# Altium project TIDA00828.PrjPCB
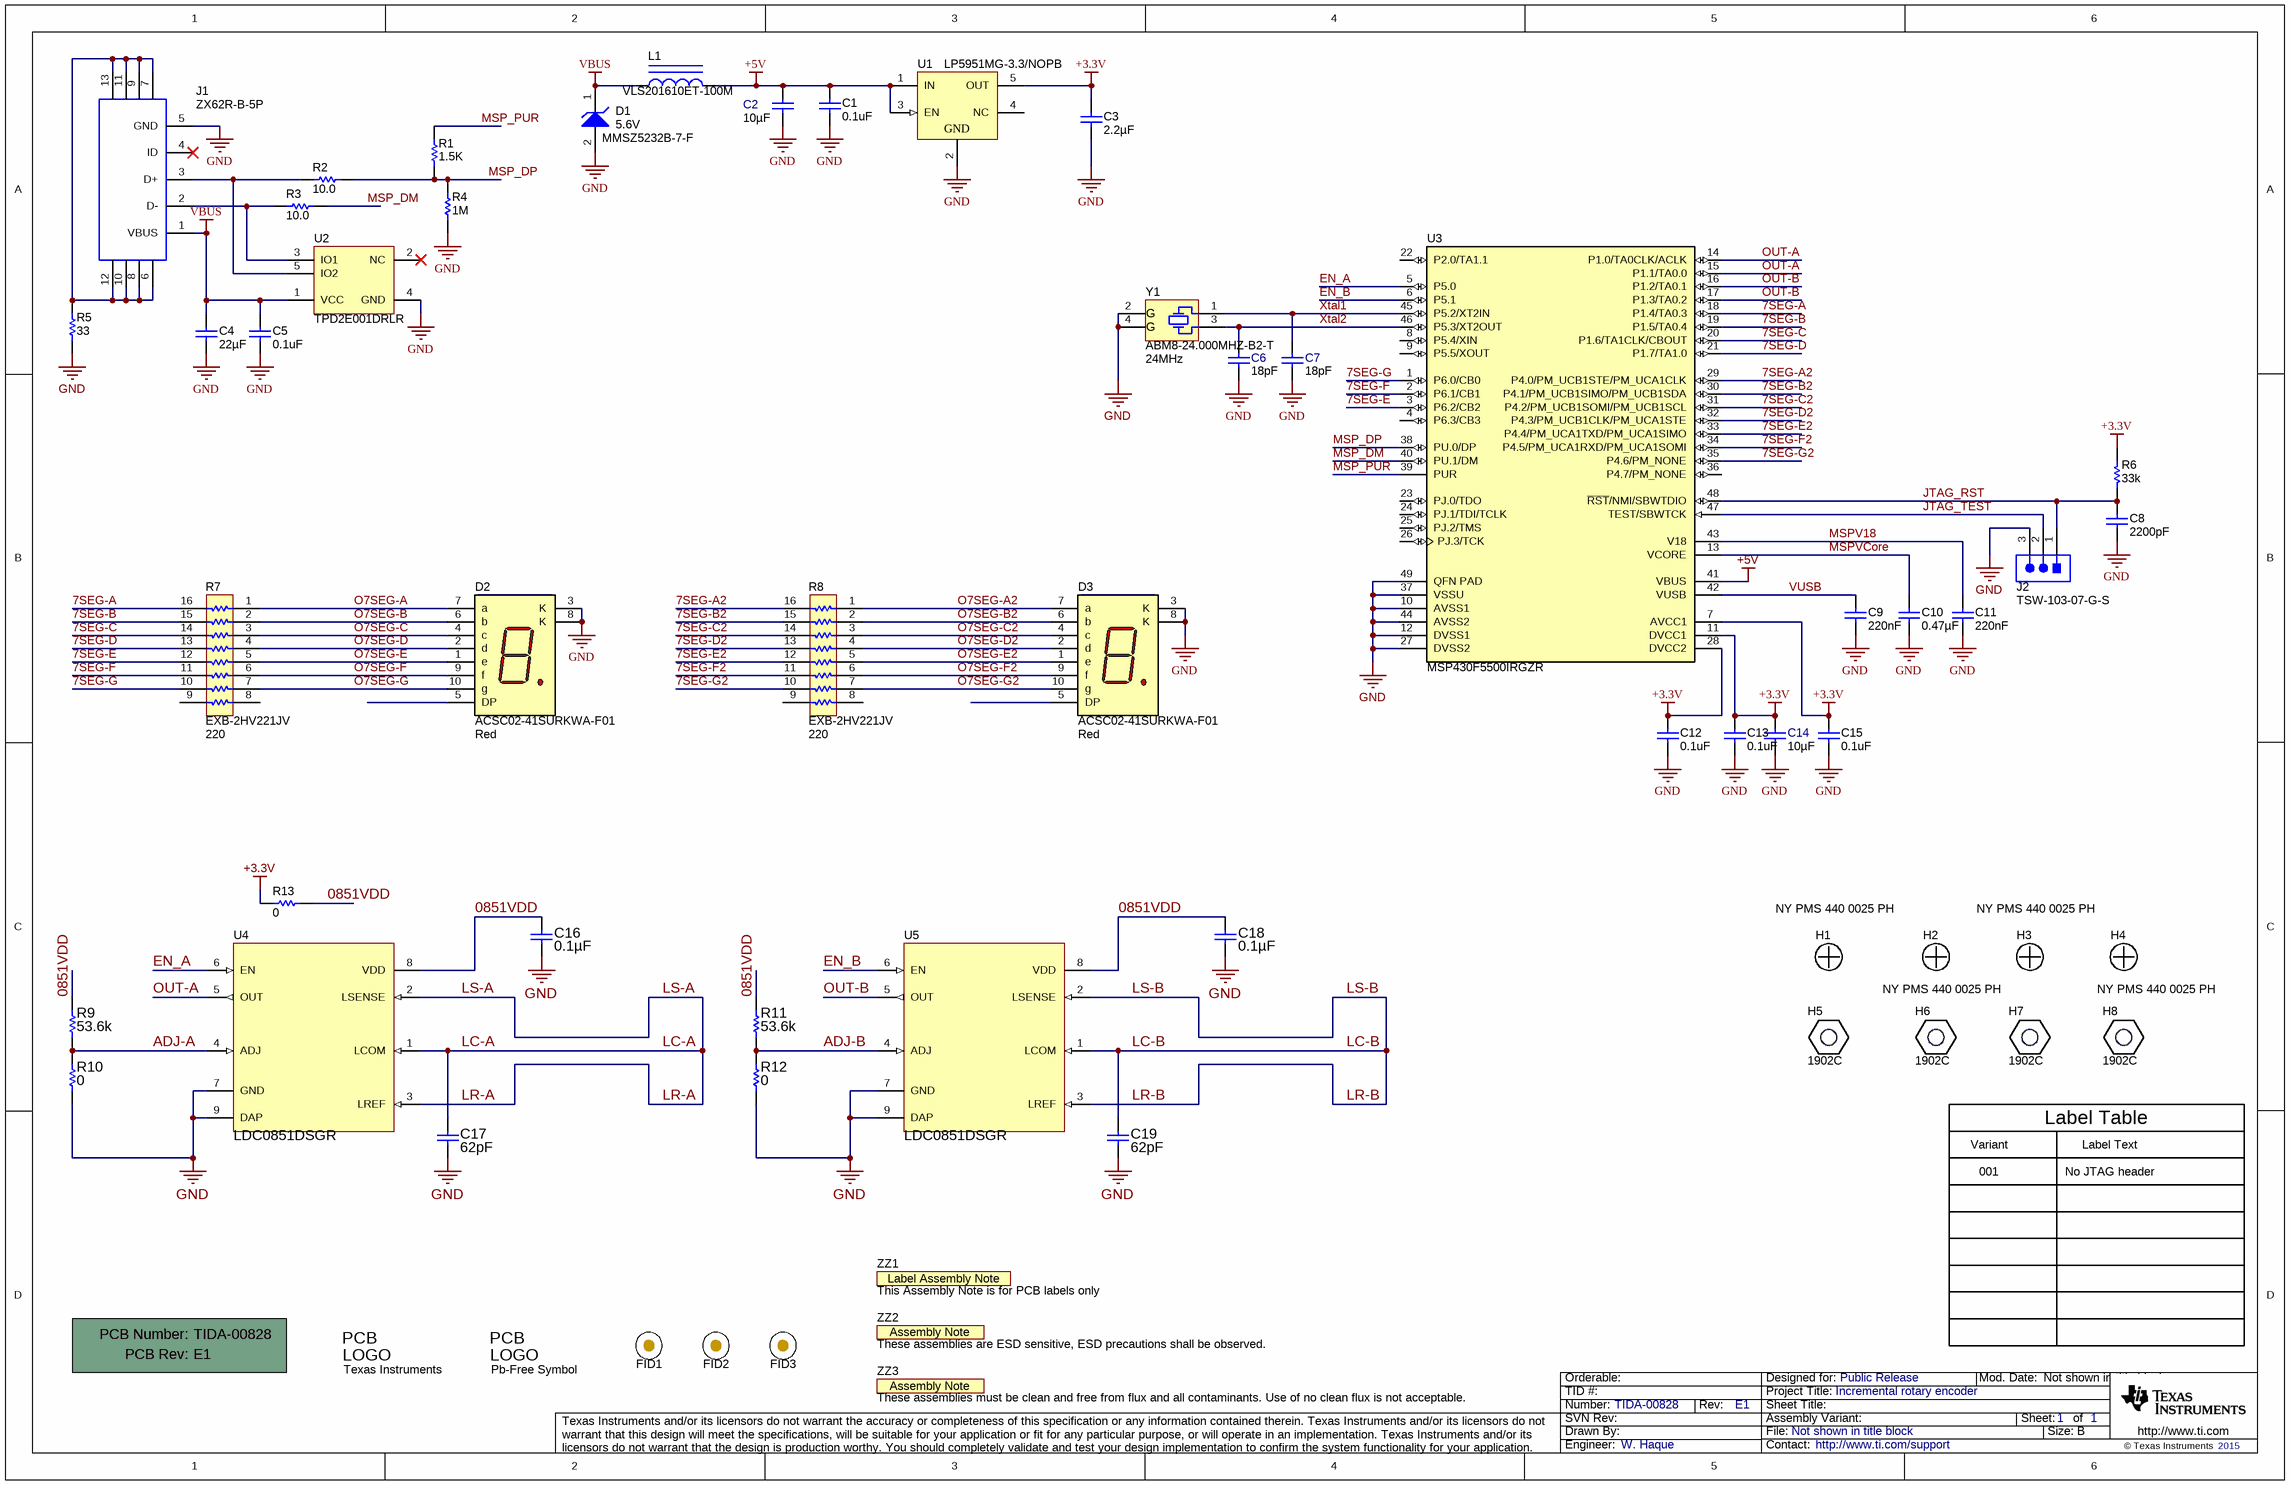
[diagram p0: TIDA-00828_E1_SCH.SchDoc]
TechSupport: http://www.ti.com/support; SCH_Rev: E1; PRJ_Title: Incremental rotary encoder; PRJ_Number: TIDA-00828; PRJ_Engineer: W. Haque; PRJ_Customer: Public Release; PCB_Rev: E1; PCB_Layout: W. Haque; CopyrightYear: 2015
1 sheet, 61 parts. Net scope: global (net labels, ports and power ports of the same name join across sheets).
Board file: TIDA-00828_E1.PcbDoc

## Sheet TIDA-00828_E1_SCH.SchDoc
size 431 x 279 mm; Date: Not shown in title block; ApprovedBy: Not shown in title block; CheckedBy: Not shown in title block; Author: Not shown in title block; CompanyName: Not shown in title block; Engineer: Not shown in title block; Organization: Not shown in title block; Address1: Not shown in title block; Address2: Not shown in title block; Address3: Not shown in title block; Address4: Not shown in title block; DocumentNumber: 1; Revision: Use project parameter SCH_Rev; SheetNumber: 1; SheetTotal: 1; PageSetup: Record=PageOptions¦CenterHorizontal=True¦CenterVertical=True¦PrintScale=1.00¦XCorrection=1.00¦YCorrection=1.00¦PrintKind=0¦BorderSize=5000000¦LeftOffset=0¦BottomOffset=0¦Orientation=2¦PaperLength=1000¦PaperWidth=1000¦Scale=100¦PaperSource=15¦PrintQuality=600¦MediaType=1¦DitherType=10¦PaperKind=Letter¦PrintScaleMode=1

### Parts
!PCB1  Printed Circuit Board  (value not drawn)  (mechanical)
C1  value 0.1uF  [0402]  (hidden comment: GRM155R71C104JA88D)
C2  ValueDisplayed: 10µF  [0603]  (hidden comment: C1608X5R1A106M)
C3  ValueDisplayed: 2.2µF  [0603]  (hidden comment: C0603C225K8PACTU)
C4  ValueDisplayed: 22µF  [0805_HV]  (hidden comment: C2012X5R1C226K125AC)
C5  value 0.1uF  [0402]  (hidden comment: GRM155R71C104JA88D)
C6  ValueDisplayed: 18pF  [0603]  (hidden comment: GRM1885C2A180JA01D)
C7  ValueDisplayed: 18pF  [0603]  (hidden comment: GRM1885C2A180JA01D)
C8  ValueDisplayed: 2200pF  [0603]  (hidden comment: C0603X222K5RACTU)
C9  value 220nF  [0402]  (hidden comment: C1005X7R1A224K050BB)
C10  ValueDisplayed: 0.47µF  [0402]  (hidden comment: GRM155R60J474KE19D)
C11  value 220nF  [0402]  (hidden comment: C1005X7R1A224K050BB)
C12  value 0.1uF  [0402]  (hidden comment: GRM155R71C104JA88D)
C13  value 0.1uF  [0402]  (hidden comment: GRM155R71C104JA88D)
C14  ValueDisplayed: 10µF  [0603]  (hidden comment: C1608X5R1A106M)
C15  value 0.1uF  [0402]  (hidden comment: GRM155R71C104JA88D)
C16  ValueDisplayed: 0.1µF  [0402]  (hidden comment: GRM155R71C104KA88D)
C17  ValueDisplayed: 62pF  [0402]  (hidden comment: GRM1555C1H620JA01D)
C18  ValueDisplayed: 0.1µF  [0402]  (hidden comment: GRM155R71C104KA88D)
C19  ValueDisplayed: 62pF  [0402]  (hidden comment: GRM1555C1H620JA01D)
D1  MMSZ5232B-7-F  value 5.6V  [SOD-123]
D2  ACSC02-41SURKWA-F01  value Red  [ACSC02-41_Red]
D3  ACSC02-41SURKWA-F01  value Red  [ACSC02-41_Red]
FID1  Fiducial  [Fiducial10-20]  (value not drawn)
FID2  Fiducial  [Fiducial10-20]  (value not drawn)
FID3  Fiducial  [Fiducial10-20]  (value not drawn)
H1  NY PMS 440 0025 PH  [NY PMS 440 0025 PH]
H2  NY PMS 440 0025 PH  [NY PMS 440 0025 PH]
H3  NY PMS 440 0025 PH  [NY PMS 440 0025 PH]
H4  NY PMS 440 0025 PH  [NY PMS 440 0025 PH]
H5  1902C  [Keystone_1902C]
H6  1902C  [Keystone_1902C]
H7  1902C  [Keystone_1902C]
H8  1902C  [Keystone_1902C]
J1  ZX62R-B-5P  [Hirose_ZX62R-B-5P]
J2  TSW-103-07-G-S  [TSW-103-07-G-S]
L1  VLS201610ET-100M  [VLS201610ET]
Logo1  Texas Instruments  [TI_Stacked_Overlay_Small]  (no BOM)
Logo2  Pb-Free Symbol  [Pb-Free_Overlay_Small]  (no BOM)
R1  value 1.5K  [0402]  (hidden comment: CRCW04021K50JNED)
R2  ValueDisplayed: 10.0  [0402]  (hidden comment: CRCW040210R0FKED)
R3  ValueDisplayed: 10.0  [0402]  (hidden comment: CRCW040210R0FKED)
R4  value 1M  [0402]  (hidden comment: RC0402JR-071ML)
R5  value 33  [0603]  (hidden comment: CRCW060333R0JNEA)
R6  value 33k  [0402]  (hidden comment: CRCW040233K0JNED)
R7  EXB-2HV221JV  ValueDisplayed: 220  [RESCAXS_EXB-2HV]
R8  EXB-2HV221JV  ValueDisplayed: 220  [RESCAXS_EXB-2HV]
R9  ValueDisplayed: 53.6k  [0402]  (hidden comment: CRCW040253K6FKED)
R10  ValueDisplayed: 0  [0402]  (hidden comment: RC0402JR-070RL)
R11  ValueDisplayed: 53.6k  [0402]  (hidden comment: CRCW040253K6FKED)
R12  ValueDisplayed: 0  [0402]  (hidden comment: RC0402JR-070RL)
R13  ValueDisplayed: 0  [0402]  (hidden comment: RC0402JR-070RL)
U1  LP5951MG-3.3/NOPB  [MAA05A_N]
U2  TPD2E001DRLR  [DRL0005A]
U3  MSP430F5500IRGZR  [RGZ0048A]
U4  LDC0851DSGR  [DSG0008A]
U5  LDC0851DSGR  [DSG0008A]
Y1  ABM8-24.000MHZ-B2-T  Frequency: 24MHz  [XTAL_ABM8]
ZZ1  This Assembly Note is for PCB labels only  [AssemblyNoteLabel]  (no BOM)
ZZ2  These assemblies are ESD sensitive, ESD precautions shall be observed.  [AssemblyNote]  (no BOM)
ZZ3  These assemblies must be clean and free from flux and all contaminants. Use of no clean flux is not acceptable.  [AssemblyNote]  (no BOM)

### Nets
+3.3V: C3.1 C12.1 C13.1 C14.1 C15.1 R6.1 R13.1 U1.5(OUT) U3.7(AVCC1) U3.11(DVCC1) U3.28(DVCC2)
+5V: C1.1 C2.1 L1.2 U1.1(IN) U1.3(EN) U3.41(VBUS)
GND: C1.2 C2.2 C3.2 C4.2 C5.2 C6.1 C7.1 C8.1 C9.2 C10.2 C11.2 C12.2 C13.2 C14.2 C15.2 C16.2 C17.2 C18.2 C19.2 D1.2(A) D2.3(K) D2.8(K) D3.3(K) D3.8(K) J1.5(GND) J2.3 R4.1 R5.1 R10.1 R12.1 U1.2(GND) U2.4(GND) U3.10(AVSS1) U3.12(DVSS1) U3.27(DVSS2) U3.37(VSSU) U3.44(AVSS2) U3.49(QFN_PAD) U4.7(GND) U4.9(DAP) U5.7(GND) U5.9(DAP) Y1.2(GND) Y1.4(GND)
VBUS: C4.1 C5.1 D1.1(K) J1.1(VBUS) L1.1 U2.1(VCC)
7SEG-A: R7.16 U3.18(P1.4/TA0.3)
7SEG-A2: R8.16 U3.29(P4.0/PM_UCB1STE/PM_UCA1CLK)
7SEG-B: R7.15 U3.19(P1.5/TA0.4)
7SEG-B2: R8.15 U3.30(P4.1/PM_UCB1SIMO/PM_UCB1SDA)
7SEG-C: R7.14 U3.20(P1.6/TA1CLK/CBOUT)
7SEG-C2: R8.14 U3.31(P4.2/PM_UCB1SOMI/PM_UCB1SCL)
7SEG-D: R7.13 U3.21(P1.7/TA1.0)
7SEG-D2: R8.13 U3.32(P4.3/PM_UCB1CLK/PM_UCA1STE)
7SEG-E: R7.12 U3.3(P6.2/CB2)
7SEG-E2: R8.12 U3.33(P4.4/PM_UCA1TXD/PM_UCA1SIMO)
7SEG-F: R7.11 U3.2(P6.1/CB1)
7SEG-F2: R8.11 U3.34(P4.5/PM_UCA1RXD/PM_UCA1SOMI)
7SEG-G: R7.10 U3.1(P6.0/CB0)
7SEG-G2: R8.10 U3.35(P4.6/PM_NONE)
0851VDD: C16.1 C18.1 R9.2 R11.2 R13.2 U4.8(VDD) U5.8(VDD)
ADJ-A: R9.1 R10.2 U4.4(ADJ)
ADJ-B: R11.1 R12.2 U5.4(ADJ)
EN_A: U3.5(P5.0) U4.6(EN)
EN_B: U3.6(P5.1) U5.6(EN)
JTAG_RST: C8.2 J2.1 R6.2 U3.48(~{RST}/NMI/SBWTDIO)
JTAG_TEST: J2.2 U3.47(TEST/SBWTCK)
LC-A: C17.1 U4.1(LCOM) U4.2(LSENSE) U4.3(LREF)  [also labelled LR-A, LS-A]
LC-B: C19.1 U5.1(LCOM) U5.2(LSENSE) U5.3(LREF)  [also labelled LR-B, LS-B]
MSP_DM: R3.2 U3.40(PU.1/DM)
MSP_DP: R1.1 R2.2 R4.2 U3.38(PU.0/DP)
MSP_PUR: R1.2 U3.39(PUR)
MSPV18: C11.1 U3.43(V18)
MSPVCore: C10.1 U3.13(VCORE)
O7SEG-A: D2.7(a) R7.1
O7SEG-A2: D3.7(a) R8.1
O7SEG-B: D2.6(b) R7.2
O7SEG-B2: D3.6(b) R8.2
O7SEG-C: D2.4(c) R7.3
O7SEG-C2: D3.4(c) R8.3
O7SEG-D: D2.2(d) R7.4
O7SEG-D2: D3.2(d) R8.4
O7SEG-E: D2.1(e) R7.5
O7SEG-E2: D3.1(e) R8.5
O7SEG-F: D2.9(f) R7.6
O7SEG-F2: D3.9(f) R8.6
O7SEG-G: D2.10(g) R7.7
O7SEG-G2: D3.10(g) R8.7
OUT-A: U3.14(P1.0/TA0CLK/ACLK) U3.15(P1.1/TA0.0) U4.5(OUT)
OUT-B: U3.16(P1.2/TA0.1) U3.17(P1.3/TA0.2) U5.5(OUT)
VUSB: C9.1 U3.42(VUSB)
Xtal1: C7.2 U3.45(P5.2/XT2IN) Y1.1
Xtal2: C6.2 U3.46(P5.3/XT2OUT) Y1.3
NetJ1_2: J1.2(D-) R3.1 U2.3(IO1)
NetJ1_3: J1.3(D+) R2.1 U2.5(IO2)
NetJ1_6: J1.6 J1.7 J1.8 J1.9 J1.10 J1.11 J1.12 J1.13 R5.2

Not connected (* = marked no-connect by the designer): D2 5(DP); D3 5(DP); J1 4(ID)*; R7 8 9; R8 8 9; U1 4(NC); U2 2(NC)*; U3 4(P6.3/CB3) 8(P5.4/XIN) 9(P5.5/XOUT) 22(P2.0/TA1.1) 23(PJ.0/TDO) 24(PJ.1/TDI/TCLK) 25(PJ.2/TMS) 26(PJ.3/TCK) 36(P4.7/PM_NONE)

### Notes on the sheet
- Variant
- 001
- Label Table
- Label Text
- No JTAG header

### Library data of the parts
!PCB1 = PCB: Manufacturer: Any; PartNumber: TIDA-00828; SymbolCreator: a0412235
C1 C5 C12 C13 C15 = 0402YC132KAT2A: CAP CER 0.1UF 16V 5% X7R 0402; Manufacturer: Murata Electronics North America; Polarized: N; CompType: Capacitor; U/M: EA; Cap_F: 0.0000000013; Tolerance_%: 10; VDC_V: 16; TaMin_C: -55; TaMax_C: 125
C2 C14 = C1608X5R1A106M: CAP, CERM, 10uF, 10V, +/-20%, X5R, 0603; Manufacturer: TDK; Polarized: N; CompType: Capacitor; U/M: EA; Cap_F: 0.00001; Tolerance_%: 20; ESR_Ohm: 0.0078; Value1: 0.0078 ohm; VDC_V: 10; IRMS_A: 1.85; TaMin_C: -55; TaMax_C: 85
C3 = C0603C225K8PACTU: CAP, CERM, 2.2uF, 10V, +/-10%, X5R, 0603; Manufacturer: Kemet; Polarized: N; CompType: Capacitor; U/M: EA; Cap_F: 0.0000022; Tolerance_%: 10; Value1: Unknown; TaMin_C: -55; TaMax_C: 85
C4 = C2012X5R1C226K125AC: CAP, CERM, 22uF, 16V, +/-10%, X5R, 0805; Manufacturer: TDK; Polarized: N; CompType: Capacitor; U/M: EA; Cap_F: 0.000022; Tolerance_%: 10; Value1: Unknown; VDC_V: 16; TaMin_C: -55; TaMax_C: 85; Cap_Case: 0805
C6 C7 = GRM1885C2A180JA01D: CAP, CERM, 18pF, 100V, +/-5%, C0G/NP0, 0603; Manufacturer: MuRata; Polarized: N; CompType: Capacitor; U/M: EA; Cap_F: 0.000000000018; Tolerance_%: 5; Value1: Unknown; VDC_V: 100; TaMin_C: -55; TaMax_C: 125
C8 = C0603X222K5RACTU: CAP, CERM, 2200pF, 50V, +/-10%, X7R, 0603; Manufacturer: Kemet; Polarized: N; CompType: Capacitor; U/M: EA; Cap_F: 0.0000000022; Tolerance_%: 10; VDC_V: 50; TaMin_C: -55; TaMax_C: 125
C9 C11 = 0402YC132KAT2A: CAP, CERM, 220nF, 10V, 10%, X7R, 0402; Manufacturer: TDK Corporation; Polarized: N; CompType: Capacitor; U/M: EA; Cap_F: 0.00000022; Tolerance_%: 10; TaMin_C: -55; TaMax_C: 125
C10 = GRM155R60J474KE19D: CAP, CERM, 0.47 µF, 6.3 V, +/- 10%, X5R, 0402; Manufacturer: MuRata; Polarized: N; CompType: Capacitor; Value: 0.47uF; U/M: EA; Cap_F: 0.00000047; Tolerance_%: 10; Value1: Unknown; VDC_V: 6.3; Value2: 6.3V; TaMin_C: -55; TaMax_C: 85
C16 C18 = GRM155R71C104KA88D: CAP, CERM, 0.1 µF, 16 V, +/- 10%, X7R, 0402; Manufacturer: MuRata; Polarized: N; CompType: Capacitor; Value: 0.1uF; U/M: EA; Cap_F: 0.0000001; Tolerance_%: 10; Value1: Unknown; VDC_V: 16; Value2: 16V; TaMin_C: -55; TaMax_C: 125; AEC Category: Q200
C17 C19 = GRM1555C1H620JA01D: CAP, CERM, 62 pF, 50 V, +/- 5%, C0G/NP0, 0402; Manufacturer: MuRata; Polarized: N; CompType: Capacitor; Value: 62pF; U/M: EA; Cap_F: 0.000000000062; Tolerance_%: 5; Value1: Unknown; VDC_V: 50; Value2: 50V; TaMin_C: -55; TaMax_C: 125; AEC Category: Q200
D1 = MMSZ5232B-7-F: Diode, Zener, 5.6V, 500mW, SOD-123; Manufacturer: Diodes Inc.; U/M: EA; Power_W: 0.5; Vz_V: 5.6; Value1: 0.5W; RJA_CperW: 350
D2 D3 = ACSC02-41SURKWA-F01: LED, Red, SMD; Manufacturer: Kingbright; SymbolCreator: Altium; Vf_V: 1.95; Value2: 1.95V; Io_A: 0.02; Vr_V: 5; Ir_A: 1e-005; Tjmax_C: 85; Power_TotalModule: 0.075; Value1: 0.075W; U/M: EA
FID1-FID3 = Fiducial: Fiducial mark.  There is nothing to buy or mount.; SymbolCreator: codlsc
H1-H4 = NY PMS 440 0025 PH: Machine Screw, Round, #4-40 x 1/4, Nylon, Philips panhead; Manufacturer: B&F Fastener Supply; CompType: Hardware; SymbolCreator: codlsc; U/M: EA
H5-H8 = 1902C: Standoff, Hex, 0.5"L #4-40 Nylon; Manufacturer: Keystone; CompType: Hardware; SymbolCreator: a0412235
J1 = ZX62R-B-5P: Connector, Receptacle, Micro-USB Type B, SMT; Manufacturer: Hirose Electric Co. Ltd.; SymbolCreator: a0799628; U/M: EA
J2 = TSW-103-07-G-S: Header, 100mil, 3x1, Gold, TH; Manufacturer: Samtec; SymbolCreator: a0799628; U/M: EA
L1 = VLS201610ET-100M: Inductor, Shielded, Ferrite, 10 µH, 0.4 A, 1.38 ohm, SMD; Manufacturer: TDK; Value: 10uH; Ind_H: 10.0E-6; ValueDisplayed: 10µH; Imax_A: 0.4; Irms: 0.42A @ 40C rise; Isat: 0.4A @ 30% inductance drop; DCR_ohm: 1.38; Value2: 0.4A
Logo1 = TI_Logo: Texas Instrument Corporate Signature; SymbolCreator: codlsc
Logo2 = Pb-Free: SymbolCreator: a0412235
R1 = CRCW040233K0JNED: RES 1.5K OHM 1/16W 5% 0402 SMD; Manufacturer: Vishay Dale; CompType: Resistor; Res_ohm: 33000; Value_Code: 33k0; Tolerance_%: 5; Power_W: 0.063; Value2: 0.063W; VDC_V: 50; TempCo: 200 ppm/C; EIA_Code: E24; U/M: EA
R2 R3 = CRCW040210R0FKED: RES, 10.0, 1%, 0.063 W, 0402; Manufacturer: Vishay-Dale; CompType: Resistor; Value: 10.0; Res_ohm: 10; Value_Code: 10R0; Tolerance_%: 1; Power_W: 0.063; Value2: 0.063W; VDC_V: 50; TempCo: 100 ppm/C; EIA_Code: E96; U/M: EA
R4 = CRCW040233K0JNED: RES,1M ohm, 5%, 0.063W, 0402; Manufacturer: Yageo; CompType: Resistor; Res_ohm: 33000; Value_Code: 33k0; Tolerance_%: 5; Power_W: 0.063; VDC_V: 50; TempCo: 200 ppm/C; EIA_Code: E24; U/M: EA
R5 = CRCW060333R0JNEA: RES, 33 ohm, 5%, 0.1W, 0603; Manufacturer: Vishay-Dale; CompType: Resistor; Value_Code: 33R0; Tolerance_%: 5; Power_W: 0.1; VDC_V: 75; TempCo: 200 ppm/C; EIA_Code: E24; U/M: EA
R6 = CRCW040233K0JNED: RES, 33k ohm, 5%, 0.063W, 0402; Manufacturer: Vishay-Dale; CompType: Resistor; Res_ohm: 33000; Value_Code: 33k0; Tolerance_%: 5; Power_W: 0.063; VDC_V: 50; TempCo: 200 ppm/C; EIA_Code: E24; U/M: EA
R7 R8 = EXB-2HV681JV: RES, 220, 5%, 0.0625 W, Resistor Array - 8x1; Manufacturer: Panasonic; SymbolCreator: a0411947; Res_ohm: 680; Value: 220; Value_Code: 220R; Tolerance_%: 5; Power_W: 0.0625; TempCo: 200 ppm/C; EIA_Code: E24; U/M: EA
R9 R11 = CRCW040253K6FKED: RES, 53.6 k, 1%, 0.063 W, 0402; Manufacturer: Vishay-Dale; CompType: Resistor; Value: 53.6k; Res_ohm: 53600; Value_Code: 53k6; Tolerance_%: 1; Power_W: 0.063; Value2: 0.063W; VDC_V: 50; TempCo: 100 ppm/C; EIA_Code: E96; U/M: EA; AEC Category: Q200
R10 R12 R13 = RC0402JR-070RL: RES, 0, 5%, 0.063 W, 0402; Manufacturer: Yageo America; CompType: Resistor; Value: 0; Value_Code: 0000; Tolerance_%: 5; Power_W: 0.063; Value2: 0.063W; VDC_V: 50; TempCo: 200 ppm/C; EIA_Code: E24; U/M: EA; AEC Category: Q200
U1 = LP5951MG-3.3/NOPB: Micropower, 150mA Low-Dropout CMOS Voltage Regulator, 5-pin SC-70, Pb-Free; Manufacturer: Texas Instruments; PackageTopMarking: LAB*XTT; PowerWise: N; CompType: LDO IC
U2 = TPD2E001DRLR: Low-Capacitance + / - 15 kV ESD-Protection Array for High-Speed Data Interfaces, 2 Channels, -40 to +85 degC, 5-pin SOT (DRL), Green (RoHS & no Sb/Br); Manufacturer: Texas Instruments; Alternate Manufacturer: None; Alternate PartNumber: Equivalent; Breakdown Voltage(Min)(V): 11; IEC 61000-4-2 Air-Gap(+/- kV): 15; IEC 61000-4-2 Contact(+/- kV): 8; IO Capacitance(Typ)(pF): 1.5; IO Leakage Current(nA): 1; SubFamily: ESD Solution; USB High Speed: TRUE
U3 = MSP430F5500IRGZR: 25 MHz Mixed Signal Microcontroller with 8 KB Flash, 4096 B SRAM and 31 GPIOs, -40 to 85 degC, 48-pin QFN (RGZ), Green (RoHS & no Sb/Br); Alternate Manufacturer: Texas Instruments; Alternate PartNumber: Equivalent; Brown Out Reset: Yes; DMA: 3; Flash(KB): 8; Frequency(MHz): 25; GPIO: 31; Multiplier: 32x32; Pin/Package: 48VQFN; SRAM(B): 4096; SubFamily: 5 Series; Timers - 16-bit: 4; USB: 1
U4 U5 = LDC0851DSGR: 1.8-3.3V Inductive Switch, DSG0008A; Alternate PartNumber: LDC0851DSGT; Manufacturer: Texas Instruments; SymbolCreator: Altium; CompType: IC; U/M: EA
Y1 = ABM8-24.000MHZ-B2-T: Crystal, 24.000MHz, 18pF, SMD; Manufacturer: Abracon Corportation; SymbolCreator: a0412235; U/M: EA; TaMin_C: -20; TaMax_C: 70; Frequency Stability: ±50ppm
ZZ1 = AssemblyNoteLabel: SymbolCreator: a0412235
ZZ2 ZZ3 = AssemblyNote: SymbolCreator: codlsc

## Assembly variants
001: not fitted FID1 FID2 FID3 H1 H2 H3 H4 H5 H6 H7 H8 J2 R9 R11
